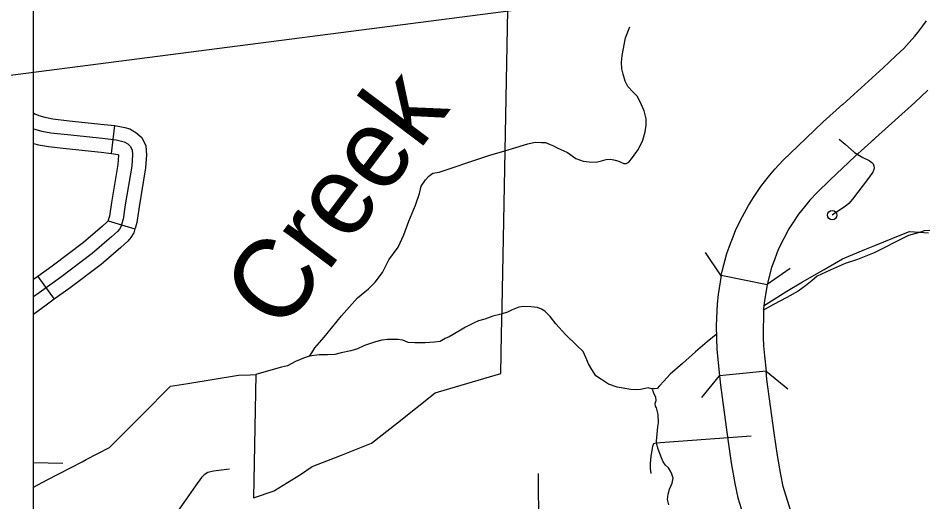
# Model space of a CAD drawing. Extents: x 670147 to 673275, y 705573 to 707613.
# Drawn here: x 671148.3 to 671245.2, y 706232.1 to 706283.8 of the extents above; entities that cross this region are included whole.
import ezdxf

# ---------------------------------------------------------------- set-up
doc = ezdxf.new("R2010")
doc.units = 0
for name, color, linetype in [('10', 7, 'Continuous'), ('31', 7, 'Continuous'), ('32', 7, 'Continuous'), ('33', 7, 'Continuous'), ('35', 7, 'Continuous'), ('37', 7, 'Continuous'), ('5', 7, 'Continuous'), ('6', 7, 'Continuous'), ('Default', 7, 'Continuous'), ('R_NoPlot', 7, 'Continuous')]:
    doc.layers.add(name, color=color, linetype=linetype)

msp = doc.modelspace()

# ---------------------------------------------------------------- linework, layer by layer
at = {"layer": '10'}
for points in [[(671236.47, 706274.576), (671240.793, 706278.471), (671242.153, 706279.747), (671243.01, 706280.541), (671243.565, 706281.172), (671244.178, 706281.861), (671244.495, 706282.241), (671245.034, 706282.95), (671245.432, 706283.515)], [(671245.564, 706276.09), (671244.177, 706274.79), (671239.625, 706270.689)], [(671228.377, 706255.307), (671223.478, 706256.307), (671223.573, 706256.772), (671224.083, 706258.643), (671224.47, 706259.729), (671224.746, 706260.435), (671225.03, 706261.226), (671225.737, 706262.601), (671226.383, 706263.783), (671226.906, 706264.636), (671227.7, 706265.817), (671228.507, 706266.817), (671229.212, 706267.652), (671230.109, 706268.626), (671231.678, 706270.124), (671234.367, 706272.693), (671236.492, 706274.595)], [(671239.827, 706270.87), (671237.763, 706269.022), (671235.131, 706266.508), (671233.678, 706265.121), (671232.962, 706264.344), (671232.363, 706263.633), (671231.728, 706262.847), (671231.114, 706261.933), (671230.71, 706261.275), (671230.154, 706260.259), (671229.626, 706259.23), (671229.429, 706258.682), (671229.155, 706257.98), (671228.856, 706257.143), (671228.439, 706255.614), (671228.377, 706255.307)], [(671223.478, 706256.307), (671223.132, 706254.275), (671223.022, 706253.259), (671222.94, 706250.953)], [(671228.377, 706255.307), (671228.09, 706253.612), (671227.995, 706252.739), (671227.954, 706249.69)], [(671222.94, 706250.953), (671222.955, 706249.582), (671222.993, 706248.395), (671223.297, 706245.582)], [(671227.954, 706249.69), (671227.984, 706248.772), (671228.11, 706247.718), (671228.273, 706246.076)], [(671246.909, 706210.006), (671242.002, 706215.338), (671238.537, 706219.209), (671237.195, 706220.72), (671235.947, 706222.165), (671235.184, 706223.119), (671234.56, 706223.947), (671233.913, 706224.888), (671233.476, 706225.689), (671232.803, 706226.872), (671232.277, 706227.922), (671231.797, 706228.984), (671231.435, 706229.824), (671231.038, 706230.755), (671230.772, 706231.569), (671230.376, 706232.841), (671230.102, 706233.77), (671229.828, 706235.034), (671229.486, 706237.053), (671229.133, 706239.486), (671228.362, 706245.174), (671228.273, 706246.076), (671223.297, 706245.582)], [(671223.297, 706245.582), (671223.396, 706244.591), (671224.181, 706238.792), (671224.546, 706236.277), (671224.917, 706234.086), (671225.254, 706232.532), (671225.591, 706231.39), (671226.009, 706230.048), (671226.354, 706228.994), (671226.839, 706227.854), (671227.224, 706226.963), (671227.762, 706225.773), (671228.39, 706224.515), (671229.108, 706223.254), (671229.647, 706222.268), (671230.502, 706221.023), (671231.235, 706220.052), (671232.101, 706218.969), (671233.433, 706217.426), (671234.806, 706215.882), (671238.299, 706211.978), (671243.234, 706206.616), (671244.915, 706204.797), (671247.915, 706201.677)]]:
    msp.add_lwpolyline(points, dxfattribs=at)
at = {"layer": '31'}
for points in [[(671170.866, 706235.623), (671169.183, 706235.393), (671168.578, 706235.249), (671168.175, 706235.004), (671167.888, 706234.73), (671167.24, 706233.838), (671165.994, 706232.053), (671164.526, 706229.98), (671163.878, 706229.081), (671163.634, 706228.778), (671163.317, 706228.519), (671159.906, 706226.518), (671159.066, 706225.947), (671153.009, 706222.361), (671149.935, 706220.486)], [(671203.898, 706235.134), (671203.937, 706229.39), (671203.951, 706225.234), (671203.951, 706224.643), (671203.863, 706224.377), (671203.733, 706224.048)]]:
    msp.add_lwpolyline(points, dxfattribs=at)
at = {"layer": '32'}
for p, q in [((671158.277, 706269.324), (671158.633, 706272.303)), ((671157.895, 706262.127), (671160.768, 706261.266)), ((671150.396, 706256.201), (671152.138, 706253.759))]:
    msp.add_line(p, q, dxfattribs=at)
for points in [[(671149.935, 706273.679), (671150.08, 706273.574), (671150.479, 706273.37), (671151.137, 706273.191), (671151.991, 706273.029), (671153.737, 706272.833), (671157.486, 706272.44), (671158.633, 706272.303)], [(671149.935, 706271.964), (671149.935, 706271.964), (671150.799, 706271.728), (671151.768, 706271.545), (671153.575, 706271.342), (671157.319, 706270.949), (671158.746, 706270.779), (671159.322, 706270.661), (671159.623, 706270.569), (671160.003, 706270.346), (671160.278, 706270.111), (671160.461, 706269.731), (671160.513, 706269.181), (671160.422, 706267.989), (671159.741, 706263.848), (671159.518, 706262.303), (671159.348, 706261.753), (671159.27, 706261.491), (671159.113, 706261.255), (671158.903, 706260.993), (671158.275, 706260.43), (671156.206, 706258.649), (671152.802, 706256.076), (671150.528, 706254.453), (671149.935, 706254.002)], [(671158.633, 706272.303), (671158.986, 706272.261), (671159.692, 706272.116), (671160.229, 706271.953), (671160.877, 706271.573), (671161.492, 706271.045), (671161.929, 706270.141), (671162.019, 706269.195), (671161.912, 706267.81), (671161.223, 706263.62), (671160.986, 706261.972), (671160.783, 706261.316), (671160.768, 706261.266)], [(671149.935, 706270.409), (671150.462, 706270.265), (671151.544, 706270.06), (671153.413, 706269.851), (671157.152, 706269.458), (671158.277, 706269.324)], [(671158.277, 706269.324), (671158.506, 706269.297), (671158.952, 706269.205), (671159.006, 706269.189), (671159.008, 706269.167), (671158.931, 706268.169), (671158.258, 706264.077), (671158.051, 706262.633), (671157.913, 706262.19), (671157.895, 706262.127)], [(671157.898, 706262.138), (671157.809, 706262.027), (671157.285, 706261.557), (671155.263, 706259.817), (671151.914, 706257.285), (671150.396, 706256.201)], [(671160.768, 706261.265), (671160.642, 706260.845), (671160.325, 706260.369), (671159.997, 706259.959), (671159.265, 706259.303), (671157.149, 706257.481), (671153.69, 706254.867), (671152.138, 706253.759)], [(671150.396, 706256.201), (671149.935, 706255.872)], [(671152.138, 706253.759), (671151.417, 706253.244), (671149.935, 706252.12)]]:
    msp.add_lwpolyline(points, dxfattribs=at)
at = {"layer": '33'}
for points in [[(671236.065, 706270.857), (671236.706, 706270.341), (671237.734, 706269.432), (671238.63, 706268.895), (671239.299, 706268.572), (671239.586, 706268.357), (671239.705, 706268.213), (671239.789, 706268.022), (671239.836, 706267.807), (671239.801, 706267.604), (671239.669, 706267.317), (671239.108, 706266.552), (671237.507, 706264.438), (671237.113, 706263.996), (671236.73, 706263.662), (671236.109, 706263.279), (671235.344, 706262.753)], [(671226.657, 706239.139), (671216.479, 706238.37), (671216.213, 706238.311), (671216.124, 706238.045), (671215.932, 706237.011), (671215.873, 706236.228), (671215.858, 706235.696), (671215.925, 706235.144)]]:
    msp.add_lwpolyline(points, dxfattribs=at)
msp.add_circle((671235.344, 706262.753), 0.5, dxfattribs=at)
at = {"layer": '35'}
for points in [[(671212.872, 706279.798), (671213.238, 706281.691), (671213.681, 706282.866)], [(671179.443, 706247.682), (671179.686, 706248.034), (671179.999, 706248.582), (671181.018, 706249.706), (671182.871, 706251.978), (671184.569, 706253.911), (671185.743, 706254.877), (671186.475, 706255.582), (671187.258, 706256.601), (671187.937, 706257.959), (671188.929, 706259.317), (671189.529, 706260.649), (671190.078, 706262.094), (671190.757, 706263.818), (671191.201, 706265.071), (671191.383, 706265.855), (671191.827, 706266.508), (671192.193, 706266.9), (671192.637, 706267.213), (671193.305, 706267.344), (671194.793, 706267.84), (671196.464, 706268.415), (671198.71, 706269.146), (671200.329, 706269.616), (671201.504, 706269.982), (671202.783, 706270.374), (671203.566, 706270.53), (671204.245, 706270.504), (671204.689, 706270.504), (671205.185, 706270.295), (671205.525, 706270.139), (671205.916, 706269.93), (671207.023, 706269.434), (671207.911, 706268.781), (671208.721, 706268.52), (671209.347, 706268.441), (671210.078, 706268.389), (671210.653, 706268.546), (671211.175, 706268.676), (671211.671, 706268.729), (671212.115, 706268.624), (671212.533, 706268.52), (671212.82, 706268.363), (671213.055, 706268.258), (671213.29, 706268.258), (671213.577, 706268.389), (671213.995, 706268.885), (671214.621, 706269.773), (671215.091, 706270.74), (671215.353, 706271.654), (671215.457, 706272.359), (671215.457, 706273.038), (671215.222, 706273.869), (671214.961, 706274.522), (671214.752, 706274.914), (671214.491, 706275.462), (671214.021, 706275.932), (671213.499, 706276.481), (671213.212, 706277.055), (671212.977, 706277.813), (671212.846, 706278.387), (671212.82, 706279.093), (671212.872, 706279.798)], [(671245.794, 706261.102), (671245.164, 706261.084), (671244.663, 706260.898), (671243.514, 706260.565), (671242.069, 706259.86), (671240.975, 706259.304), (671239.82, 706258.713), (671238.056, 706258.006), (671236.722, 706257.561), (671235.113, 706256.859), (671233.741, 706256.21), (671233.185, 706255.765), (671232.496, 706255.207), (671231.681, 706254.632), (671230.476, 706253.946), (671229.049, 706253.205), (671227.916, 706252.549)], [(671222.942, 706249.99), (671221.953, 706249.198), (671220.726, 706248.154), (671219.342, 706246.9), (671218.011, 706245.751), (671217.332, 706245.019), (671216.862, 706244.497), (671216.601, 706244.236), (671216.339, 706244.184), (671216.026, 706244.184), (671215.661, 706244.288), (671215.321, 706244.236), (671214.825, 706244.105), (671214.355, 706244.079), (671213.807, 706244.131), (671212.345, 706244.366), (671211.431, 706244.706), (671210.674, 706245.176), (671210.073, 706245.594), (671209.629, 706246.247), (671209.29, 706246.874), (671209.002, 706247.527), (671208.715, 706248.18), (671208.036, 706248.807), (671206.809, 706250.008), (671205.791, 706251.131), (671205.172, 706251.913), (671204.598, 706252.488), (671204.232, 706252.697), (671203.814, 706252.88), (671203.109, 706252.932), (671202.326, 706252.984), (671201.83, 706252.906), (671201.125, 706252.644), (671200.629, 706252.383), (671199.924, 706252.148), (671199.036, 706251.939), (671198.175, 706251.626), (671197.496, 706251.443), (671196.895, 706251.182), (671196.138, 706250.79), (671195.407, 706250.346), (671194.378, 706249.746), (671193.96, 706249.563), (671193.412, 706249.249), (671192.811, 706249.171), (671191.819, 706249.093), (671190.697, 706249.093), (671189.992, 706249.145)], [(671189.992, 706249.145), (671189.417, 706249.38), (671188.869, 706249.458), (671188.294, 706249.458), (671187.772, 706249.458), (671187.172, 706249.38), (671186.493, 706249.197), (671185.84, 706249.014), (671185.318, 706248.831), (671184.561, 706248.466), (671183.856, 706248.257), (671182.811, 706248.022), (671182.158, 706247.865), (671181.375, 706247.839), (671180.461, 706247.839), (671179.443, 706247.682), (671178.79, 706247.473), (671177.929, 706247.107), (671177.093, 706246.637), (671176.44, 706246.507), (671175.545, 706246.246), (671173.696, 706245.717)], [(671149.935, 706233.702), (671151.377, 706234.454), (671155.11, 706236.399), (671155.538, 706236.643), (671158.062, 706237.938), (671161.529, 706241.417), (671164.582, 706244.484), (671166.413, 706244.772), (671171.836, 706245.639), (671173.093, 706245.679), (671173.696, 706245.717)], [(671216.544, 706238.596), (671216.688, 706240.123), (671216.758, 706240.565), (671216.712, 706241.45), (671216.544, 706242.146), (671216.444, 706242.348), (671216.393, 706242.625), (671216.494, 706242.927), (671216.469, 706243.292), (671216.305, 706243.632), (671216.179, 706243.947), (671216.129, 706244.085)], [(671217.849, 706231.81), (671217.723, 706232.364), (671217.803, 706232.924), (671217.954, 706233.479), (671218.231, 706234.109), (671218.319, 706234.638), (671218.193, 706235.078), (671218.042, 706235.38), (671217.828, 706235.746), (671217.526, 706236.048), (671217.274, 706236.386), (671217.085, 706236.814), (671216.708, 706237.759), (671216.544, 706238.376), (671216.544, 706238.596)]]:
    msp.add_lwpolyline(points, dxfattribs=at)
at = {"layer": '37'}
for points in [[(671223.47, 706256.265), (671221.773, 706258.74)], [(671230.859, 706257.045), (671228.385, 706255.348)], [(671228.273, 706246.076), (671230.593, 706244.175)], [(671221.396, 706243.262), (671223.297, 706245.582)]]:
    msp.add_lwpolyline(points, dxfattribs=at)
at = {"layer": '5'}
msp.add_lwpolyline([(671153.06, 706236.219), (671149.935, 706236.292)], dxfattribs=at)
at = {"layer": '6'}
for points in [[(671173.696, 706245.717), (671173.529, 706236.274), (671173.462, 706232.535), (671175.651, 706233.294), (671175.712, 706233.334), (671178.462, 706235.052), (671179.729, 706235.881), (671180.359, 706236.134), (671182.202, 706236.842), (671182.865, 706237.097), (671186.084, 706238.39), (671188.839, 706240.558), (671192.894, 706243.749), (671193.248, 706243.854), (671199.884, 706245.824), (671199.968, 706250.014), (671200.026, 706252.966), (671200.209, 706262.084), (671200.735, 706288.429)], [(671227.999, 706253.06), (671229.119, 706253.769), (671230.47, 706254.624), (671232.147, 706255.626), (671234.462, 706256.954), (671236.431, 706258.084), (671238.665, 706258.999), (671239.907, 706259.5), (671242.801, 706260.668), (671243.597, 706260.989), (671244.134, 706260.965), (671245.619, 706260.838)]]:
    msp.add_lwpolyline(points, dxfattribs=at)
at = {"layer": 'Default'}
msp.add_line((671069.5, 706267.642), (671601.781, 706336.353), dxfattribs=at)
at = {"layer": 'R_NoPlot'}
msp.add_lwpolyline([(671149.935, 706689.359), (672221.933, 706689.359), (672221.933, 705919.709), (671149.935, 705919.709)], close=True, dxfattribs=at)

# ---------------------------------------------------------------- texts
at = {"layer": '35'}
msp.add_text('Creek', height=8.448, rotation=52.96318, dxfattribs=at).set_placement((671176.409, 706250.018))

doc.saveas('drawing.dxf')
